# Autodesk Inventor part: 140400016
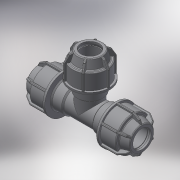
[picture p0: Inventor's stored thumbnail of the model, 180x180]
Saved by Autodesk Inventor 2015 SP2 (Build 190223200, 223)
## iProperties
Created: 2017-08
Part Number: 140400016
Material: Generic
Description: PLASSON L.14 TEE (SILVER) 16-16-16
Document SubType Name: Modeling
Designer: KIM
Density: 1 g/cm^3
Appearance: Default
Author: KIM
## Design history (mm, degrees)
derived "140400.ipt"
feature "Solid1::140400.ipt"
tag "TaggingFeature1"
body "Solid1"
other parameters: "d1" = 16, "d4" = 15 deg, "d5" = 33, "d6" = 10.89, "d10" = 39, "d16" = 16.32, "d17" = 2.5, "d22" = 25.6, "d24" = 2.5, "d25" = 35.1, "d26" = 29.25, "d27" = 2.5, "d28" = 135 deg, "d29" = 1.5, "d31" = 0.8, "d46" = 150 deg, "d49" = 1.95, "d50" = 0, "d58" = 0.48, "d61" = 360 deg, "d63" = 14.4, "d64" = 63, "d78" = 180 deg, "d80" = 23.04, "d81" = 1.28, "d84" = 2.5, "d86" = 0, "d88" = 0, "d90" = 0, "d92" = 180 deg, "d_" = 16, "G_" = 18.631, "E_" = 39, "H_" = 126, "l_2" = 19
